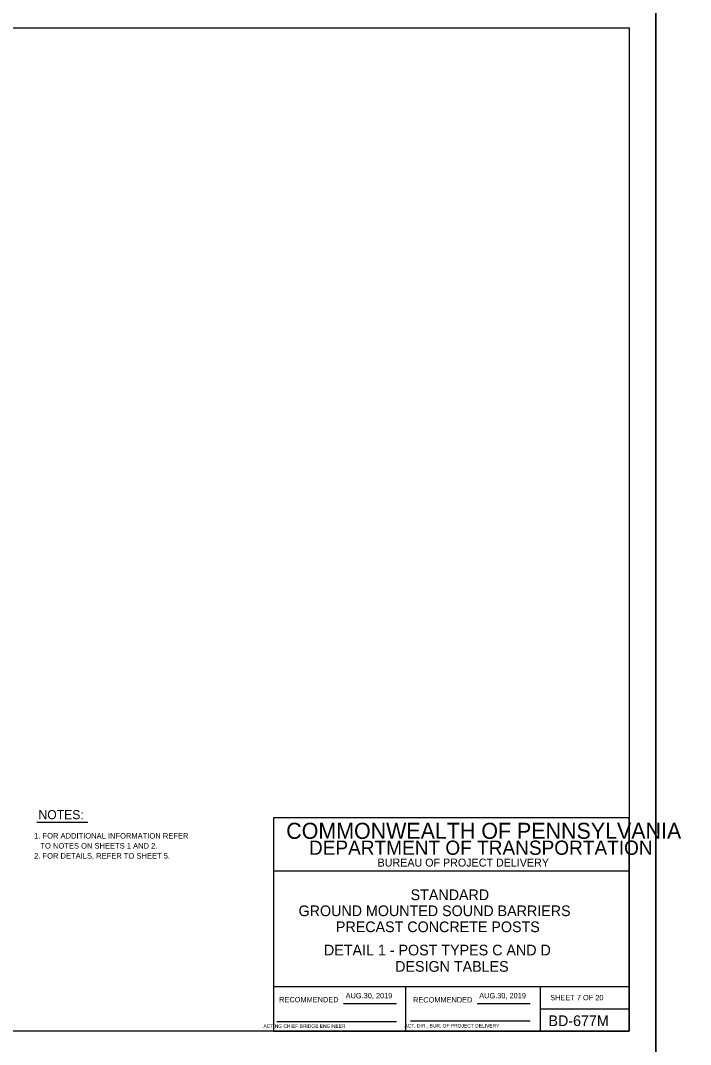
# Model space of a CAD drawing. Extents: x 3351 to 8430, y -3586 to 1457.
# Drawn here: x 6768 to 7145, y -609 to -33 of the extents above; entities that cross this region are included whole.
import ezdxf

# ---------------------------------------------------------------- set-up
doc = ezdxf.new("R2010")
doc.units = 0
for name, color, linetype in [('1', 7, 'Continuous'), ('2', 7, 'Continuous'), ('PLT-BNDY', 7, 'Continuous')]:
    doc.layers.add(name, color=color, linetype=linetype)

msp = doc.modelspace()

# ---------------------------------------------------------------- linework, layer by layer
at = {"layer": '1'}
msp.add_line((6777.47, -483.77), (6806.04, -483.77), dxfattribs=at)
at = {"layer": '2'}
for p, q in [((6324.34, -37.31), (7110.34, -37.31)), ((7110.34, -37.31), (7110.34, -601.31)), ((7110.34, -481.31), (6910.34, -481.31)), ((6910.34, -481.31), (6910.34, -601.31)), ((7110.34, -601.31), (7110.34, -481.31)), ((7110.34, -511.31), (6910.34, -511.31)), ((7110.34, -576.31), (6910.34, -576.31)), ((6984.84, -601.31), (6984.84, -576.31)), ((7060.34, -576.31), (7060.34, -601.31)), ((6949.81, -585.81), (6979.57, -585.81)), ((7024.81, -585.81), (7054.71, -585.81)), ((7060.34, -588.81), (7110.34, -588.81)), ((6912.34, -595.81), (6979.57, -595.81)), ((6987.47, -595.43), (7054.71, -595.43)), ((7110.34, -601.31), (6324.34, -601.31)), ((6910.34, -601.31), (7110.34, -601.31))]:
    msp.add_line(p, q, dxfattribs=at)
at = {"layer": 'PLT-BNDY'}
for points in [[(6284.34, -22.31), (7125.34, -22.31), (7125.34, -616.31), (6284.34, -616.31)], [(7125.34, -22.31), (7966.34, -22.31), (7966.34, -616.31), (7125.34, -616.31)]]:
    msp.add_lwpolyline(points, close=True, dxfattribs=at)

# ---------------------------------------------------------------- texts
at = {"layer": '1'}
for s, height, p in [('NOTES:', 5.117, (6778.31, -482.15)), ('1. FOR ADDITIONAL INFORMATION REFER', 3.072, (6775.86, -493.03)), ('   TO NOTES ON SHEETS 1 AND 2.', 3.072, (6775.86, -498.66)), ('2. FOR DETAILS, REFER TO SHEET 5.', 3.072, (6775.86, -504.29)), ('STANDARD', 6, (6987.48, -527.64)), ('GROUND MOUNTED SOUND BARRIERS', 6, (6924.5, -536.64)), ('PRECAST CONCRETE POSTS', 6, (6945.5, -545.64)), ('DETAIL 1 - POST TYPES C AND D', 6, (6938.79, -558.71)), ('DESIGN TABLES', 6, (6978.81, -567.91)), ('SHEET 7 OF 20', 3, (7065.96, -583.92)), ('BD-677M', 6, (7064.97, -598.43))]:
    msp.add_text(s, height=height, dxfattribs=at).set_placement(p)
at = {"layer": '2'}
for s, height, p in [('COMMONWEALTH OF PENNSYLVANIA', 9, (6917.59, -493.18)), ('DEPARTMENT OF TRANSPORTATION', 8.0002, (6930.34, -502.18)), ('BUREAU OF PROJECT DELIVERY', 4.5, (6968.93, -508.81)), ('AUG.30, 2019', 3, (6950.96, -582.83)), ('AUG.30, 2019', 3, (7026.04, -582.83)), ('       ACTING CHIEF BRIDGE ENGINEER', 2.0002, (6899.43, -599.43)), ('   ACT. DIR., BUR. OF PROJECT DELIVERY', 2.0002, (6981.7, -599.25))]:
    msp.add_text(s, height=height, dxfattribs=at).set_placement(p)
for p in [(6913.61, -585.06), (6988.83, -585.18)]:
    msp.add_text('RECOMMENDED', height=3, rotation=360, dxfattribs=at).set_placement(p)

doc.saveas('drawing.dxf')
